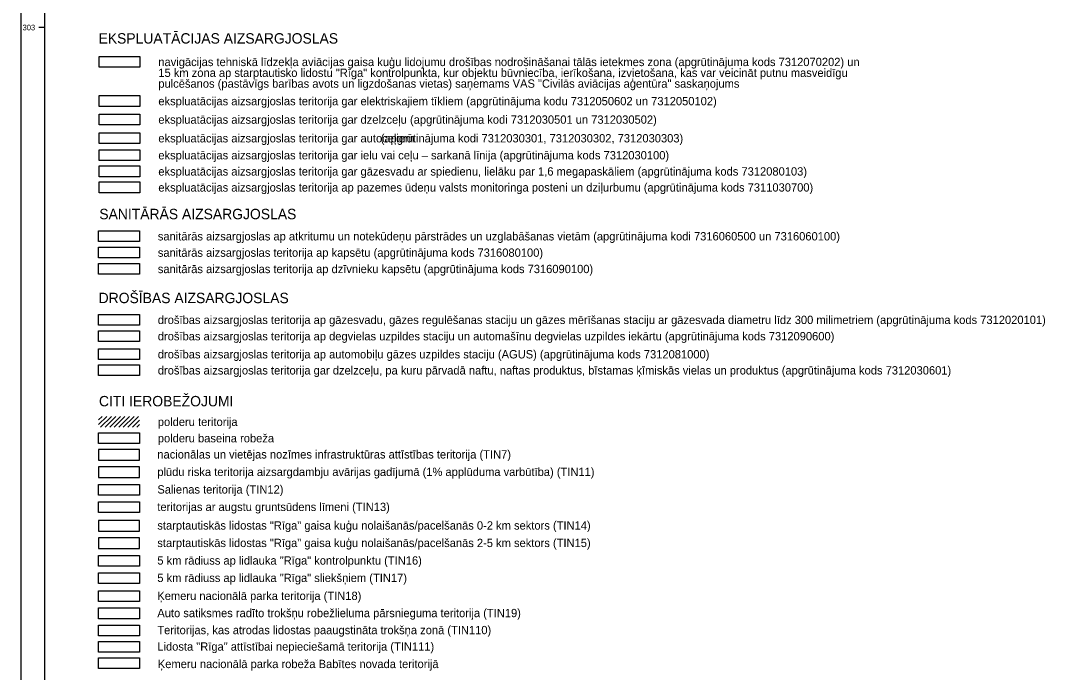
# Model space of a CAD drawing. Extents: x 468834 to 503362, y 294936 to 320859.
# Drawn here: x 468834 to 475323, y 298982 to 303042 of the extents above; entities that cross this region are included whole.
import ezdxf

# ---------------------------------------------------------------- set-up
doc = ezdxf.new("R2010")
doc.units = 0
for name, color, linetype in [('1020101_TIN11_plūdu riska teritorija', 7, 'Continuous'), ('1020102_TIN12_Salienas_teritorija', 7, 'Continuous'), ('1020103_TIN13_teritorijas ar augstu gruntsudens limeni', 7, 'Continuous'), ('1020105_TIN15_starptautiskās lidostas Rīga gaisa kuģu nolaišanās pacelšanās 2-5 km sektors', 7, 'Continuous'), ('1020106_TIN16_5 km radiuss ap lidlauku Rīga kontrolpunktu', 7, 'Continuous'), ('1020107_TIN17_5 km radiuss ap lidlauku Rīga slieksniem', 7, 'Continuous'), ('1020108_TIN18_Kemeru_nacionala_parka_teritorija', 7, 'Continuous'), ('1020109_TIN19_Auto satiksmes radīto trokšņu robežlieluma pārsnieguma teritorija', 7, 'Continuous'), ('1020110_TIN110_Lidmašīnu radīto trokšņu robežlieluma pārsnieguma teritorija', 7, 'Continuous'), ('1020700_TIN7_nacionalas_un_vietejas_nozimes_infrastrukturas_attistibas_teritorijas', 7, 'Continuous'), ('7311030700_ekspluatācijas aizsargjoslas teritorija ap pazemes ūdeņu valsts monitoringa posteni un dziļurbumu', 7, 'Continuous'), ('7312020101_drošības aizsargjoslas teritorija ap gāzesvadu gāzes regulēšanas staciju un gāzes mērīšanas staciju ar gāzesvada diametru līdz 300 milimetriem', 7, 'Continuous'), ('7312030100_ekspluatācijas aizsargjoslas teritorija gar ielu vai ceļu – sarkanā līnija', 7, 'Continuous'), ('7312030303_ekspluatācijas aizsargjoslas teritorija gar valsts vietējiem un pašvaldību autoceļiem lauku apvidos', 7, 'Continuous'), ('7312030501_ekspluatācijas aizsargjoslas teritorija gar stratēģiskas (valsts) nozīmes un reģionālas nozīmes dzelzceļa infrastruktūrā ietilpstošajiem sliežu ceļiem cierma teritorijā', 7, 'Continuous'), ('7312030601_drosibas aizsargjoslas teritorija gar dzelzcelu pa kuru parvada naftu naftas produktus bistamas kimiskas vielas un produktus', 7, 'Continuous'), ('7312050602_ekspluatācijas aizsargjoslas teritorija ap elektrisko tīklu gaisvadu līniju pilsētās un ciemos ar nominālo spriegumu 110 kilovolti', 7, 'Continuous'), ('7312070202_navigācijas tehniskā līdzekļa aviācijas gaisa kuģu lidojumu drošības nodrošināšanai tālās ietekmes zona', 7, 'Continuous'), ('7312080103_ekspluatācijas aizsargjoslas teritorija gar gāzesvadu ar spiedienu lielāku par 16 megapaskliem', 7, 'Continuous'), ('7312081000_ekspluatācijas aizsargjoslas teritorija ap automobiļu gāzes uzpildes staciju', 7, 'Continuous'), ('7312090600_drošības aizsargjoslas teritorija ap degvielas uzpildes staciju un automašīnu degvielas uzpildes iekārtu', 7, 'Continuous'), ('7316060500_sanitārās aizsargjoslas teritorija ap notekūdeņu attīrīšanas ietaisi ar atklātu notekūdeņu apstrādi un atklātiem dūņu laukiem', 7, 'Continuous'), ('7316080100_sanitārās aizsargjoslas teritorija ap kapsētu', 7, 'Continuous'), ('7316090100_sanitārās aizsargjoslas teritorija ap dzīvnieku kapsētu', 7, 'Continuous'), ('aizkrāsojums-poldera teritorija', 7, 'Continuous'), ('Nacionālā parka robeža', 7, 'Continuous'), ('Polderu_baseini', 7, 'Continuous'), ('ramis', 7, 'Continuous'), ('Teksts', 7, 'Continuous')]:
    doc.layers.add(name, color=color, linetype=linetype)

msp = doc.modelspace()

# ---------------------------------------------------------------- linework, layer by layer
at = {"layer": '1020101_TIN11_plūdu riska teritorija'}
msp.add_lwpolyline([(469318.8, 300194.8), (469572.8, 300194.8), (469572.8, 300261.6), (469318.8, 300261.6), (469318.8, 300194.8)], dxfattribs=at)
at = {"layer": '1020102_TIN12_Salienas_teritorija'}
msp.add_lwpolyline([(469318.8, 300152.2), (469572.8, 300152.2), (469572.8, 300085.4), (469318.8, 300085.4)], close=True, dxfattribs=at)
at = {"layer": '1020103_TIN13_teritorijas ar augstu gruntsudens limeni'}
msp.add_lwpolyline([(469318.8, 300043.3), (469572.8, 300043.3), (469572.8, 299976.5), (469318.8, 299976.5)], close=True, dxfattribs=at)
msp.add_lwpolyline([(469318.8, 299860.9), (469572.8, 299860.9), (469572.8, 299927.7), (469318.8, 299927.7), (469318.8, 299860.9)], dxfattribs=at)
at = {"layer": '1020105_TIN15_starptautiskās lidostas Rīga gaisa kuģu nolaišanās pacelšanās 2-5 km sektors'}
msp.add_lwpolyline([(469318.8, 299751.9), (469572.8, 299751.9), (469572.8, 299818.7), (469318.8, 299818.7), (469318.8, 299751.9)], dxfattribs=at)
at = {"layer": '1020106_TIN16_5 km radiuss ap lidlauku Rīga kontrolpunktu'}
msp.add_lwpolyline([(469318.8, 299709.3), (469572.8, 299709.3), (469572.8, 299642.5), (469318.8, 299642.5)], close=True, dxfattribs=at)
at = {"layer": '1020107_TIN17_5 km radiuss ap lidlauku Rīga slieksniem'}
msp.add_lwpolyline([(469318.8, 299600.8), (469572.8, 299600.8), (469572.8, 299533.9), (469318.8, 299533.9)], close=True, dxfattribs=at)
at = {"layer": '1020108_TIN18_Kemeru_nacionala_parka_teritorija'}
msp.add_lwpolyline([(469318.8, 299488.7), (469572.8, 299488.7), (469572.8, 299421.9), (469318.8, 299421.9)], close=True, dxfattribs=at)
at = {"layer": '1020109_TIN19_Auto satiksmes radīto trokšņu robežlieluma pārsnieguma teritorija'}
msp.add_lwpolyline([(469318.8, 299381.6), (469572.8, 299381.6), (469572.8, 299314.7), (469318.8, 299314.7)], close=True, dxfattribs=at)
at = {"layer": '1020110_TIN110_Lidmašīnu radīto trokšņu robežlieluma pārsnieguma teritorija'}
for points in [[(469318.8, 299275.6), (469572.8, 299275.6), (469572.8, 299208.7), (469318.8, 299208.7)], [(469318.8, 299172.9), (469572.8, 299172.9), (469572.8, 299106), (469318.8, 299106)]]:
    msp.add_lwpolyline(points, close=True, dxfattribs=at)
at = {"layer": '1020700_TIN7_nacionalas_un_vietejas_nozimes_infrastrukturas_attistibas_teritorijas'}
msp.add_lwpolyline([(469318.8, 300303.8), (469572.8, 300303.8), (469572.8, 300370.6), (469318.8, 300370.6), (469318.8, 300303.8)], dxfattribs=at)
msp.add_lwpolyline([(469318.8, 300303.8), (469572.8, 300303.8), (469572.8, 300370.6), (469318.8, 300370.6), (469318.8, 300303.8)], dxfattribs=at)
at = {"layer": '7311030700_ekspluatācijas aizsargjoslas teritorija ap pazemes ūdeņu valsts monitoringa posteni un dziļurbumu'}
msp.add_lwpolyline([(469322, 302037.3), (469576, 302037.3), (469576, 301970.5), (469322, 301970.5)], close=True, dxfattribs=at)
at = {"layer": '7312020101_drošības aizsargjoslas teritorija ap gāzesvadu gāzes regulēšanas staciju un gāzes mērīšanas staciju ar gāzesvada diametru līdz 300 milimetriem'}
msp.add_lwpolyline([(469318.8, 301211.8), (469572.8, 301211.8), (469572.8, 301145), (469318.8, 301145)], close=True, dxfattribs=at)
at = {"layer": '7312030100_ekspluatācijas aizsargjoslas teritorija gar ielu vai ceļu – sarkanā līnija'}
msp.add_lwpolyline([(469322, 302238), (469576, 302238), (469576, 302171.2), (469322, 302171.2)], close=True, dxfattribs=at)
at = {"layer": '7312030303_ekspluatācijas aizsargjoslas teritorija gar valsts vietējiem un pašvaldību autoceļiem lauku apvidos'}
msp.add_lwpolyline([(469322, 302343.8), (469576, 302343.8), (469576, 302276.9), (469322, 302276.9)], close=True, dxfattribs=at)
at = {"layer": '7312030501_ekspluatācijas aizsargjoslas teritorija gar stratēģiskas (valsts) nozīmes un reģionālas nozīmes dzelzceļa infrastruktūrā ietilpstošajiem sliežu ceļiem cierma teritorijā'}
msp.add_lwpolyline([(469322, 302460.3), (469576, 302460.3), (469576, 302393.4), (469322, 302393.4)], close=True, dxfattribs=at)
at = {"layer": '7312030601_drosibas aizsargjoslas teritorija gar dzelzcelu pa kuru parvada naftu naftas produktus bistamas kimiskas vielas un produktus'}
msp.add_lwpolyline([(469318.8, 300897.1), (469572.8, 300897.1), (469572.8, 300830.3), (469318.8, 300830.3)], close=True, dxfattribs=at)
at = {"layer": '7312050602_ekspluatācijas aizsargjoslas teritorija ap elektrisko tīklu gaisvadu līniju pilsētās un ciemos ar nominālo spriegumu 110 kilovolti'}
msp.add_lwpolyline([(469322, 302575.3), (469576, 302575.3), (469576, 302508.5), (469322, 302508.5)], close=True, dxfattribs=at)
at = {"layer": '7312070202_navigācijas tehniskā līdzekļa aviācijas gaisa kuģu lidojumu drošības nodrošināšanai tālās ietekmes zona'}
msp.add_lwpolyline([(469322, 302819.6), (469576, 302819.6), (469576, 302752.7), (469322, 302752.7)], close=True, dxfattribs=at)
at = {"layer": '7312080103_ekspluatācijas aizsargjoslas teritorija gar gāzesvadu ar spiedienu lielāku par 16 megapaskliem'}
msp.add_lwpolyline([(469322, 302137.2), (469576, 302137.2), (469576, 302070.3), (469322, 302070.3)], close=True, dxfattribs=at)
at = {"layer": '7312081000_ekspluatācijas aizsargjoslas teritorija ap automobiļu gāzes uzpildes staciju'}
msp.add_lwpolyline([(469318.8, 300997.3), (469572.8, 300997.3), (469572.8, 300930.4), (469318.8, 300930.4)], close=True, dxfattribs=at)
at = {"layer": '7312090600_drošības aizsargjoslas teritorija ap degvielas uzpildes staciju un automašīnu degvielas uzpildes iekārtu'}
msp.add_lwpolyline([(469318.8, 301109.9), (469572.8, 301109.9), (469572.8, 301043.1), (469318.8, 301043.1)], close=True, dxfattribs=at)
at = {"layer": '7316060500_sanitārās aizsargjoslas teritorija ap notekūdeņu attīrīšanas ietaisi ar atklātu notekūdeņu apstrādi un atklātiem dūņu laukiem'}
msp.add_lwpolyline([(469318.8, 301732.9), (469572.8, 301732.9), (469572.8, 301666), (469318.8, 301666)], close=True, dxfattribs=at)
at = {"layer": '7316080100_sanitārās aizsargjoslas teritorija ap kapsētu'}
msp.add_lwpolyline([(469318.8, 301631), (469572.8, 301631), (469572.8, 301564.1), (469318.8, 301564.1)], close=True, dxfattribs=at)
at = {"layer": '7316090100_sanitārās aizsargjoslas teritorija ap dzīvnieku kapsētu'}
msp.add_lwpolyline([(469318.8, 301529.1), (469572.8, 301529.1), (469572.8, 301462.2), (469318.8, 301462.2)], close=True, dxfattribs=at)
at = {"layer": 'aizkrāsojums-poldera teritorija'}
for p, q in [((469318.8, 300525.2), (469369.6, 300576)), ((469318.8, 300553.5), (469341.3, 300576)), ((469331, 300509.1), (469397.9, 300576)), ((469359.3, 300509.1), (469426.1, 300576)), ((469387.6, 300509.1), (469454.4, 300576)), ((469415.9, 300509.1), (469482.7, 300576)), ((469444.1, 300509.1), (469511, 300576)), ((469472.4, 300509.1), (469539.3, 300576)), ((469500.7, 300509.1), (469567.6, 300576)), ((469529, 300509.1), (469572.8, 300553)), ((469557.3, 300509.1), (469572.8, 300524.7))]:
    msp.add_line(p, q, dxfattribs=at)
at = {"layer": 'Nacionālā parka robeža'}
msp.add_lwpolyline([(469318.8, 299071.5), (469572.8, 299071.5), (469572.8, 299004.6), (469318.8, 299004.6)], close=True, dxfattribs=at)
at = {"layer": 'Polderu_baseini'}
msp.add_lwpolyline([(469318.8, 300474.1), (469572.8, 300474.1), (469572.8, 300407.2), (469318.8, 300407.2)], close=True, dxfattribs=at)
at = {"layer": 'ramis'}
for p, q in [((468983.8, 295086.2), (468983.8, 316660.3)), ((468983.8, 303000), (468945.7, 303000))]:
    msp.add_line(p, q, dxfattribs=at)
msp.add_lwpolyline([(501073.3, 316810.3), (468833.8, 316810.3), (468833.8, 294936.2), (501073.3, 294936.2)], close=True, dxfattribs=at)

# ---------------------------------------------------------------- texts
msp.add_text('303', height=35, dxfattribs=at).set_placement((468845, 302982.6))
at = {"layer": 'Teksts'}
for s, height, p in [('EKSPLUATĀCIJAS AIZSARGJOSLAS', 64.8, (469317.9, 302899.9)), ('navigācijas tehniskā līdzekļa aviācijas gaisa kuģu lidojumu drošības nodrošināšanai tālās ietekmes zona (apgrūtinājuma kods 7312070202) un', 51.84, (469690.6, 302759.5)), ('15 km zona ap starptautisko lidostu "Rīga" kontrolpunkta, kur objektu būvniecība, ierīkošana, izvietošana, kas var veicināt putnu masveidīgu ', 51.84, (469690.6, 302692.1)), ('pulcēšanos (pastāvīgs barības avots un ligzdošanas vietas) saņemams VAS "Civilās aviācijas aģentūra" saskaņojums', 51.84, (469690.6, 302624.7)), ('ekspluatācijas aizsargjoslas teritorija gar elektriskajiem tīkliem (apgrūtinājuma kodu 7312050602 un 7312050102)', 51.84, (469690.6, 302515.3)), ('ekspluatācijas aizsargjoslas teritorija gar dzelzceļu (apgrūtinājuma kodi 7312030501 un 7312030502)', 51.84, (469690.6, 302400.2)), ('ekspluatācijas aizsargjoslas teritorija gar autoceļiem', 51.84, (469690.6, 302283.8)), (' (apgrūtinājuma kodi 7312030301, 7312030302, 7312030303)', 51.84, (471057.2, 302283.8)), ('ekspluatācijas aizsargjoslas teritorija gar ielu vai ceļu – sarkanā līnija (apgrūtinājuma kods 7312030100)', 51.84, (469690.6, 302178)), ('ekspluatācijas aizsargjoslas teritorija gar gāzesvadu ar spiedienu, lielāku par 1,6 megapaskāliem (apgrūtinājuma kods 7312080103)', 51.84, (469690.6, 302077.1)), ('ekspluatācijas aizsargjoslas teritorija ap pazemes ūdeņu valsts monitoringa posteni un dziļurbumu (apgrūtinājuma kods 7311030700)', 51.84, (469690.6, 301977.3)), ('SANITĀRĀS AIZSARGJOSLAS', 64.8, (469322.8, 301805)), ('sanitārās aizsargjoslas ap atkritumu un notekūdeņu pārstrādes un uzglabāšanas vietām (apgrūtinājuma kodi 7316060500 un 7316060100)', 51.84, (469687.4, 301672.8)), ('sanitārās aizsargjoslas teritorija ap kapsētu (apgrūtinājuma kods 7316080100)', 51.84, (469687.4, 301570.9)), ('sanitārās aizsargjoslas teritorija ap dzīvnieku kapsētu (apgrūtinājuma kods 7316090100)', 51.84, (469687.4, 301469)), ('DROŠĪBAS AIZSARGJOSLAS', 64.8, (469318.7, 301281.8)), ('drošības aizsargjoslas teritorija ap gāzesvadu, gāzes regulēšanas staciju un gāzes mērīšanas staciju ar gāzesvada diametru līdz 300 milimetriem (apgrūtinājuma kods 7312020101)', 51.84, (469687.4, 301151.8)), ('drošības aizsargjoslas teritorija ap degvielas uzpildes staciju un automašīnu degvielas uzpildes iekārtu (apgrūtinājuma kods 7312090600)', 51.84, (469687.4, 301049.9)), ('drošības aizsargjoslas teritorija ap automobiļu gāzes uzpildes staciju (AGUS) (apgrūtinājuma kods 7312081000)', 51.84, (469687.4, 300937.3)), ('drošības aizsargjoslas teritorija gar dzelzceļu, pa kuru pārvadā naftu, naftas produktus, bīstamas ķīmiskās vielas un produktus (apgrūtinājuma kods 7312030601)', 51.84, (469687.4, 300837.1)), ('CITI IEROBEŽOJUMI', 64.8, (469320.8, 300638.6)), ('polderu teritorija', 51.84, (469687.4, 300515.9)), ('polderu baseina robeža', 51.84, (469687.4, 300414)), ('nacionālas un vietējas nozīmes infrastruktūras attīstības teritorija (TIN7)', 51.84, (469684.4, 300313.3)), ('plūdu riska teritorija aizsargdambju avārijas gadījumā (1% applūduma varbūtība) (TIN11)', 51.84, (469684.4, 300204.3)), ('Salienas teritorija (TIN12)', 51.84, (469684.4, 300094.9)), ('teritorijas ar augstu gruntsūdens līmeni (TIN13)', 51.84, (469684.4, 299986)), ('starptautiskās lidostas "Rīga" gaisa kuģu nolaišanās/pacelšanās 0-2 km sektors (TIN14)', 51.84, (469684.4, 299870.4)), ('starptautiskās lidostas "Rīga" gaisa kuģu nolaišanās/pacelšanās 2-5 km sektors (TIN15)', 51.84, (469684.4, 299761.4)), ('5 km rādiuss ap lidlauka "Rīga" kontrolpunktu (TIN16)', 51.84, (469684.4, 299652)), ('5 km rādiuss ap lidlauka "Rīga" sliekšņiem (TIN17)', 51.84, (469684.4, 299543.5)), ('Ķemeru nacionālā parka teritorija (TIN18)', 51.84, (469684.4, 299431.4)), ('Auto satiksmes radīto trokšņu robežlieluma pārsnieguma teritorija (TIN19)', 51.84, (469684.4, 299324.3)), ('Teritorijas, kas atrodas lidostas paaugstināta trokšņa zonā (TIN110)', 51.84, (469684.4, 299218.2)), ('Lidosta "Rīga" attīstībai nepieciešamā teritorija (TIN111)', 51.84, (469684.4, 299115.6)), ('Ķemeru nacionālā parka robeža Babītes novada teritorijā', 51.84, (469687.4, 299006.9))]:
    msp.add_text(s, height=height, dxfattribs=at).set_placement(p)

doc.saveas('drawing.dxf')
